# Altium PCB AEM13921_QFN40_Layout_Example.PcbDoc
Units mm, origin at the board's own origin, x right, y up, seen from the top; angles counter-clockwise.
Board outline 76 x 49 mm, 4 copper layers (Component Side, Ground Plane, Power Plane, Solder Side), stack 1.563 mm thick; 19 components, 42 nets, 78 pads, 29 vias.
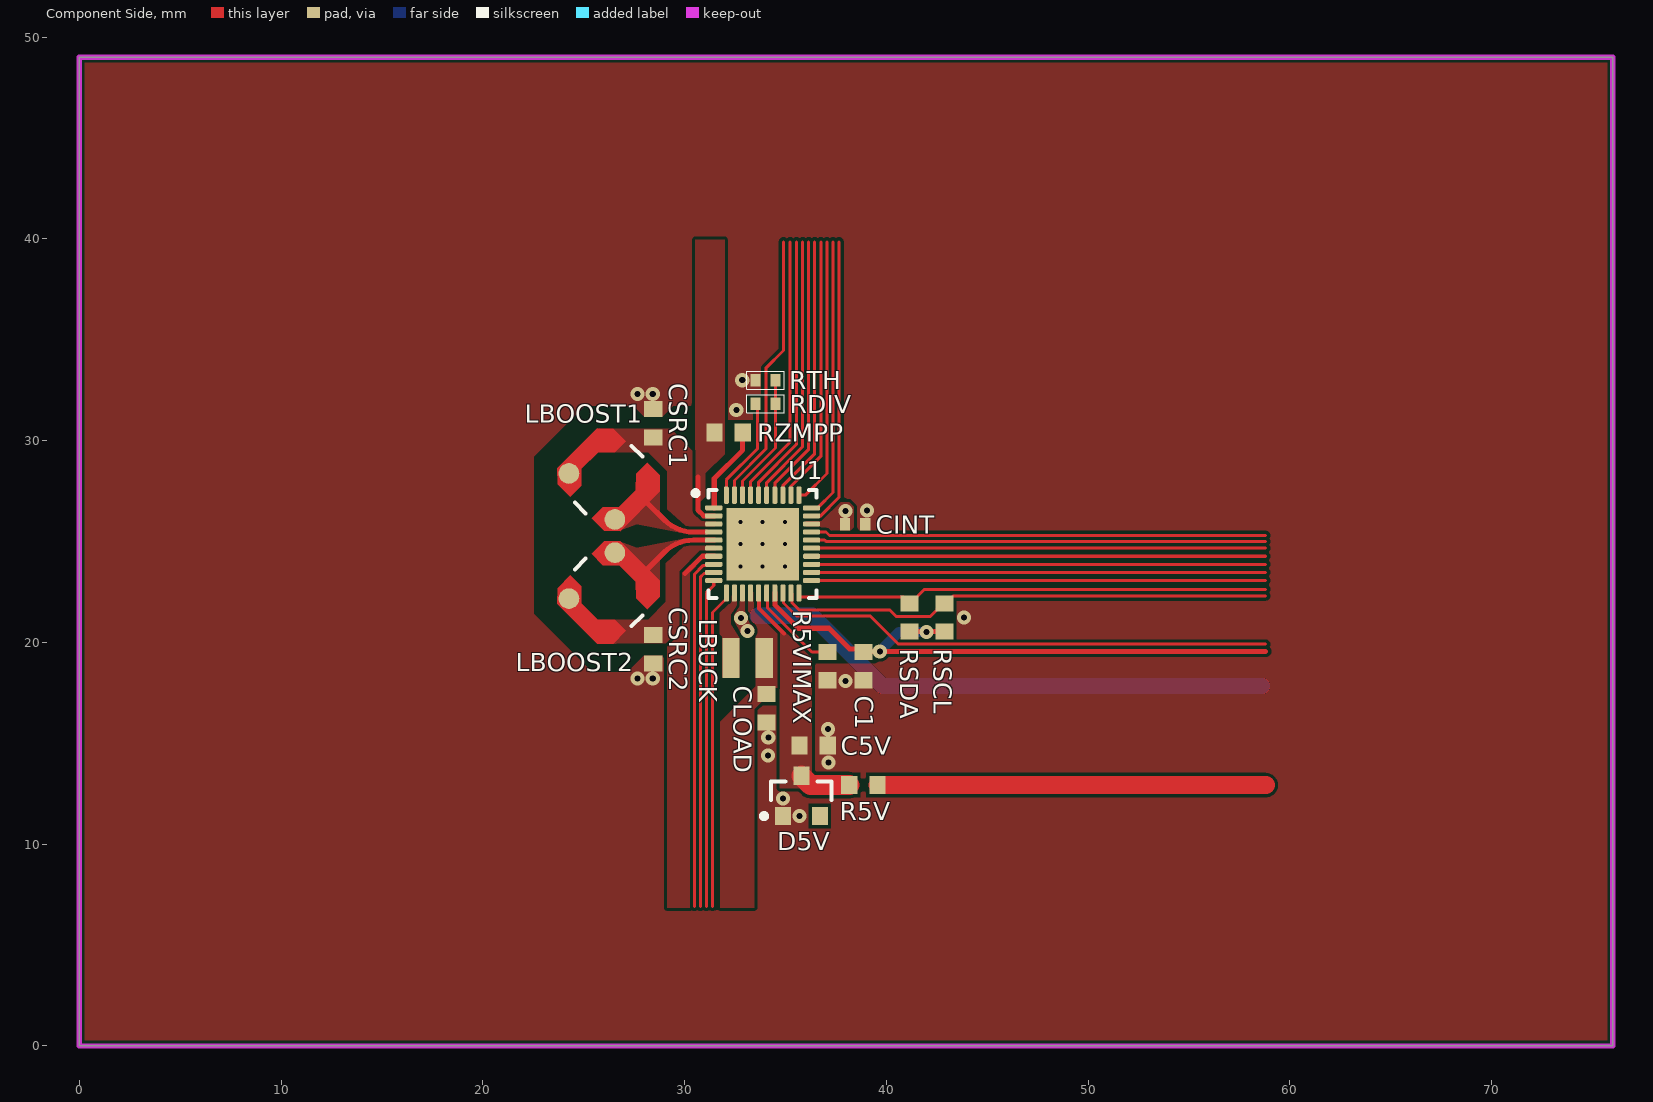
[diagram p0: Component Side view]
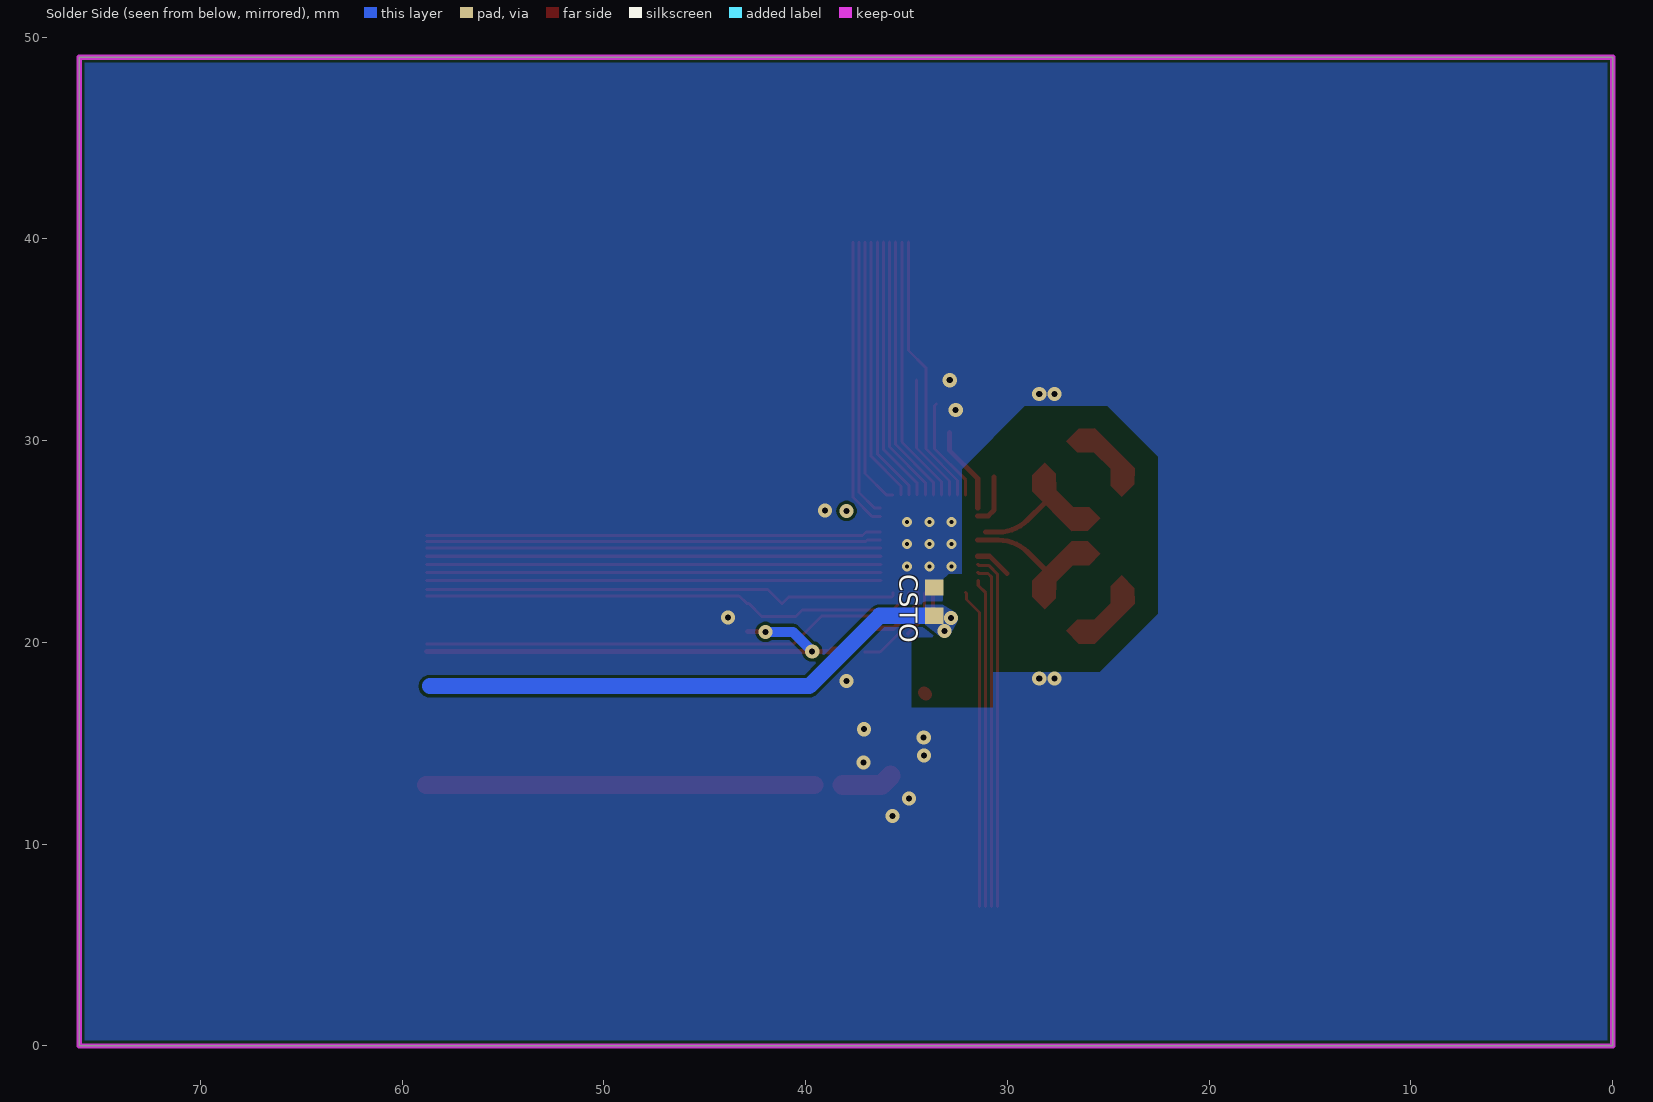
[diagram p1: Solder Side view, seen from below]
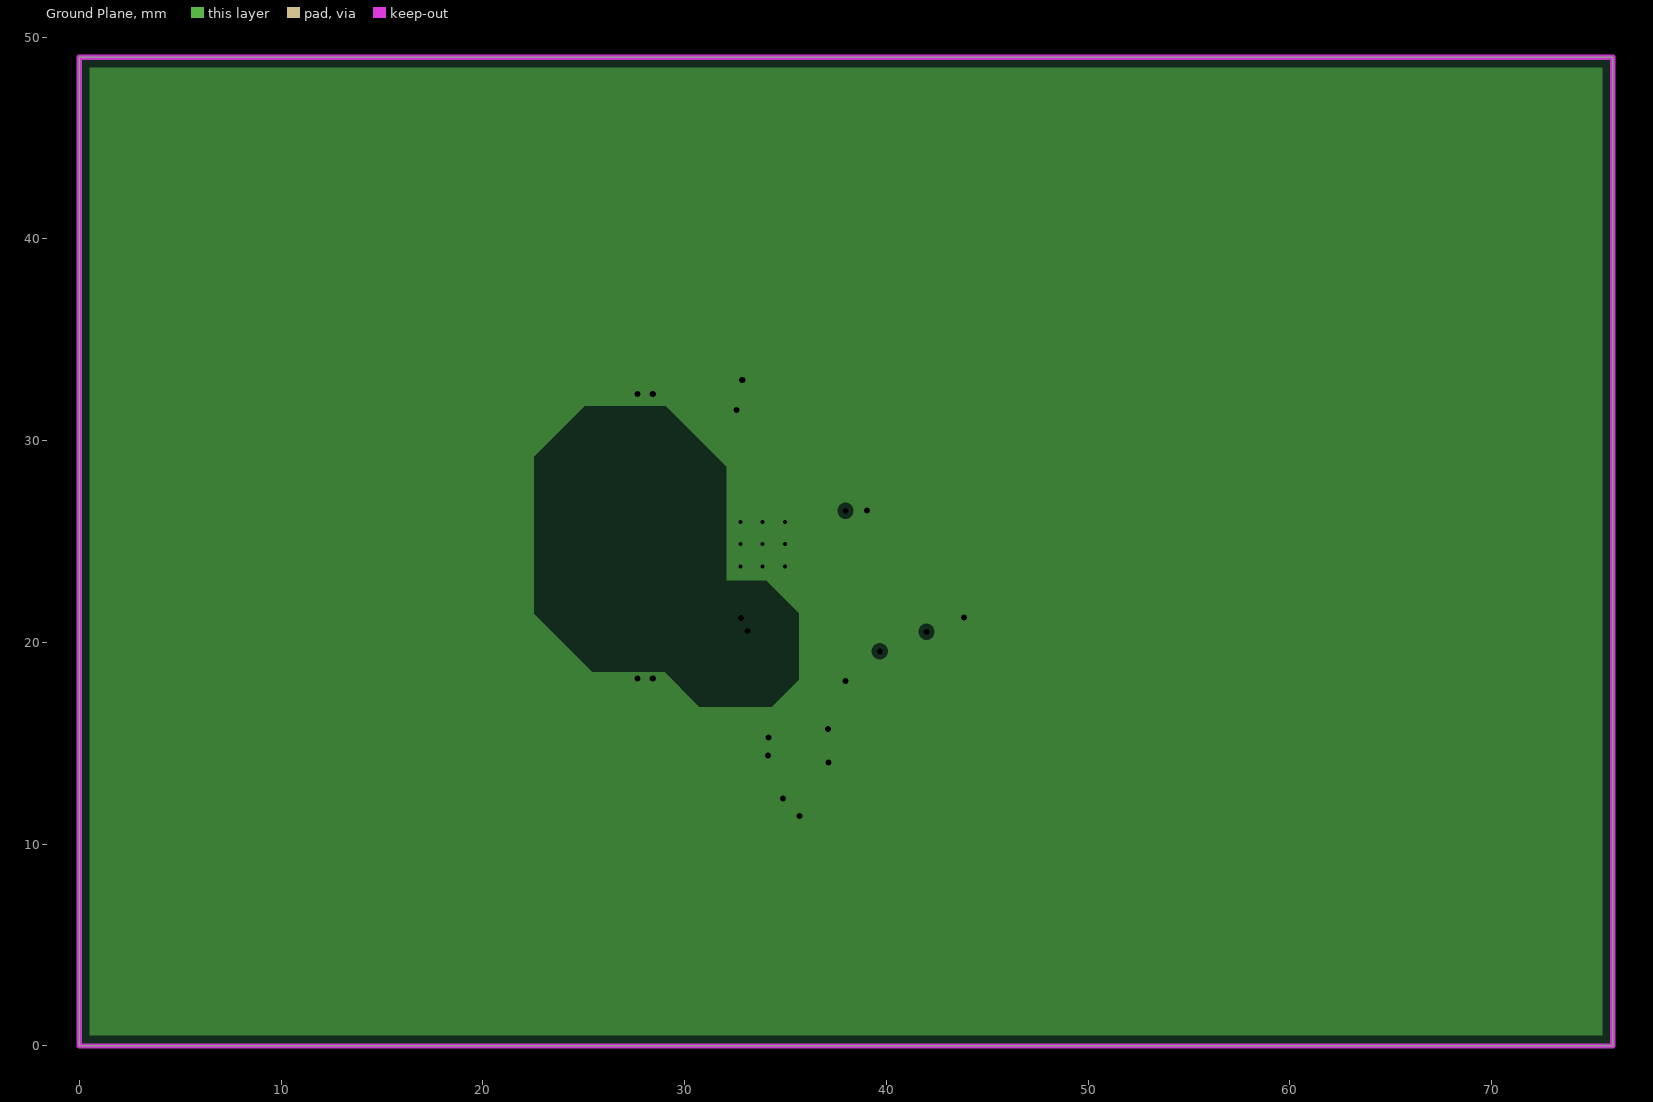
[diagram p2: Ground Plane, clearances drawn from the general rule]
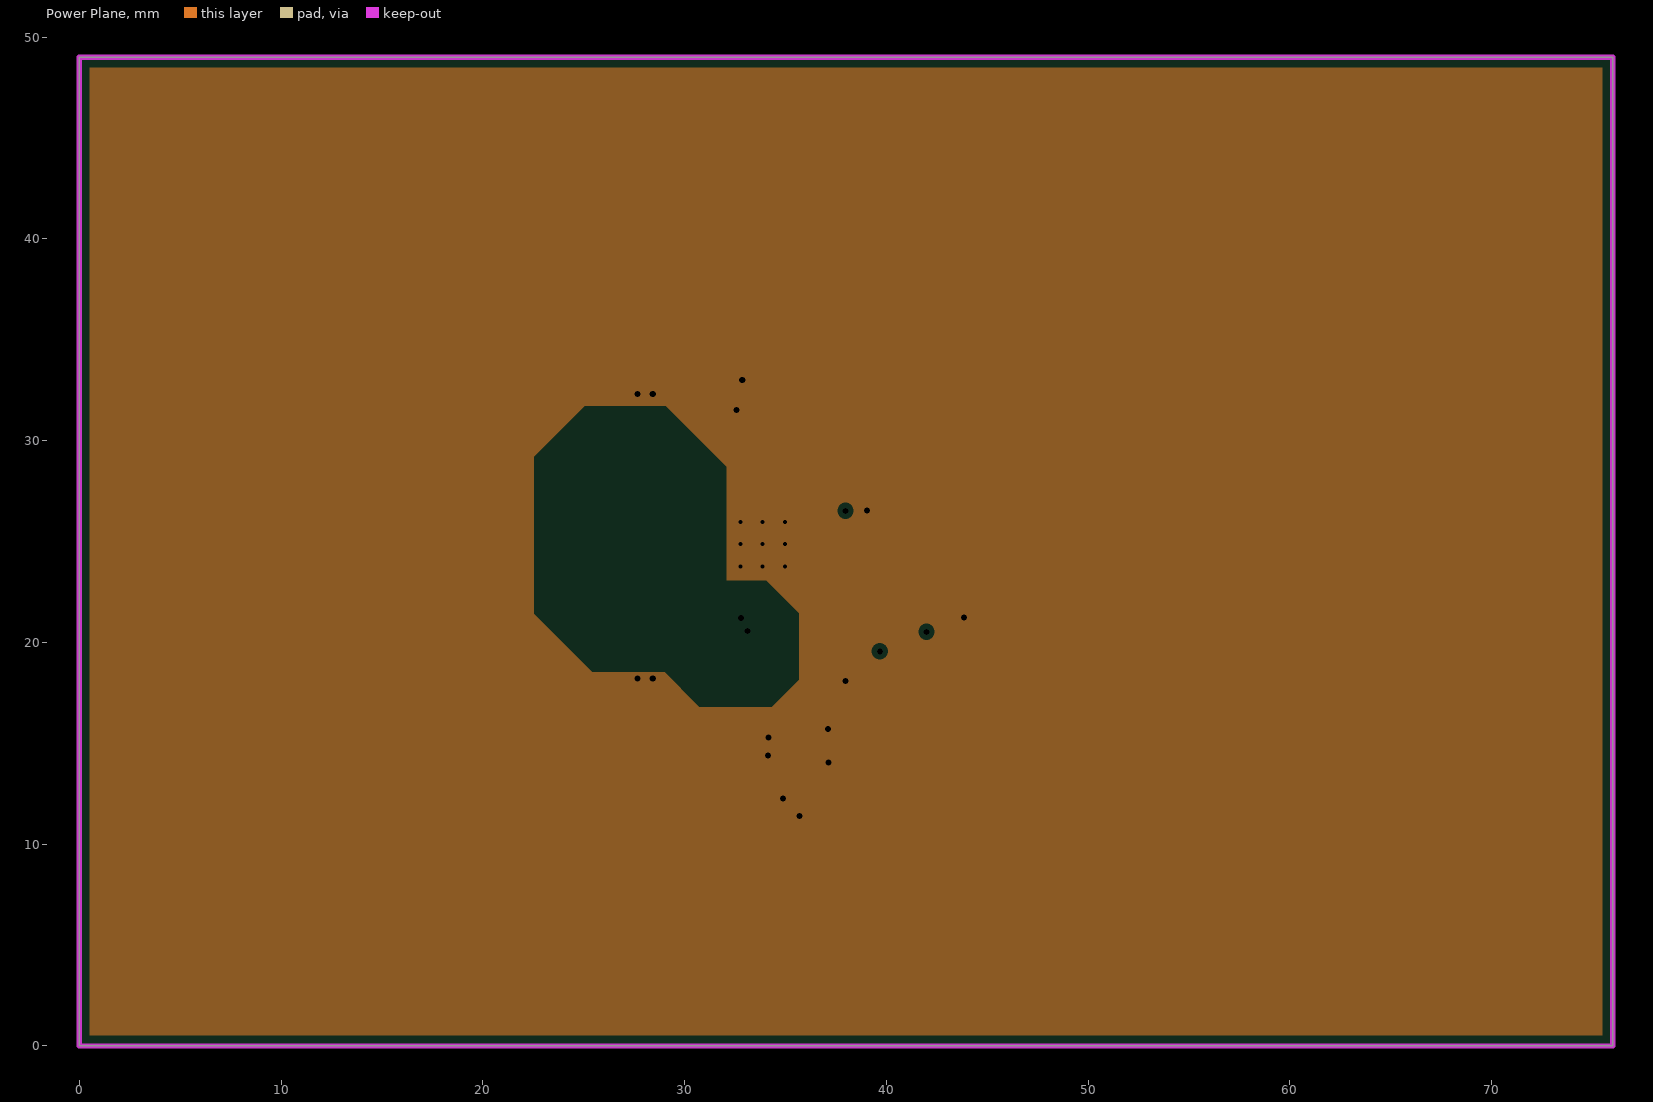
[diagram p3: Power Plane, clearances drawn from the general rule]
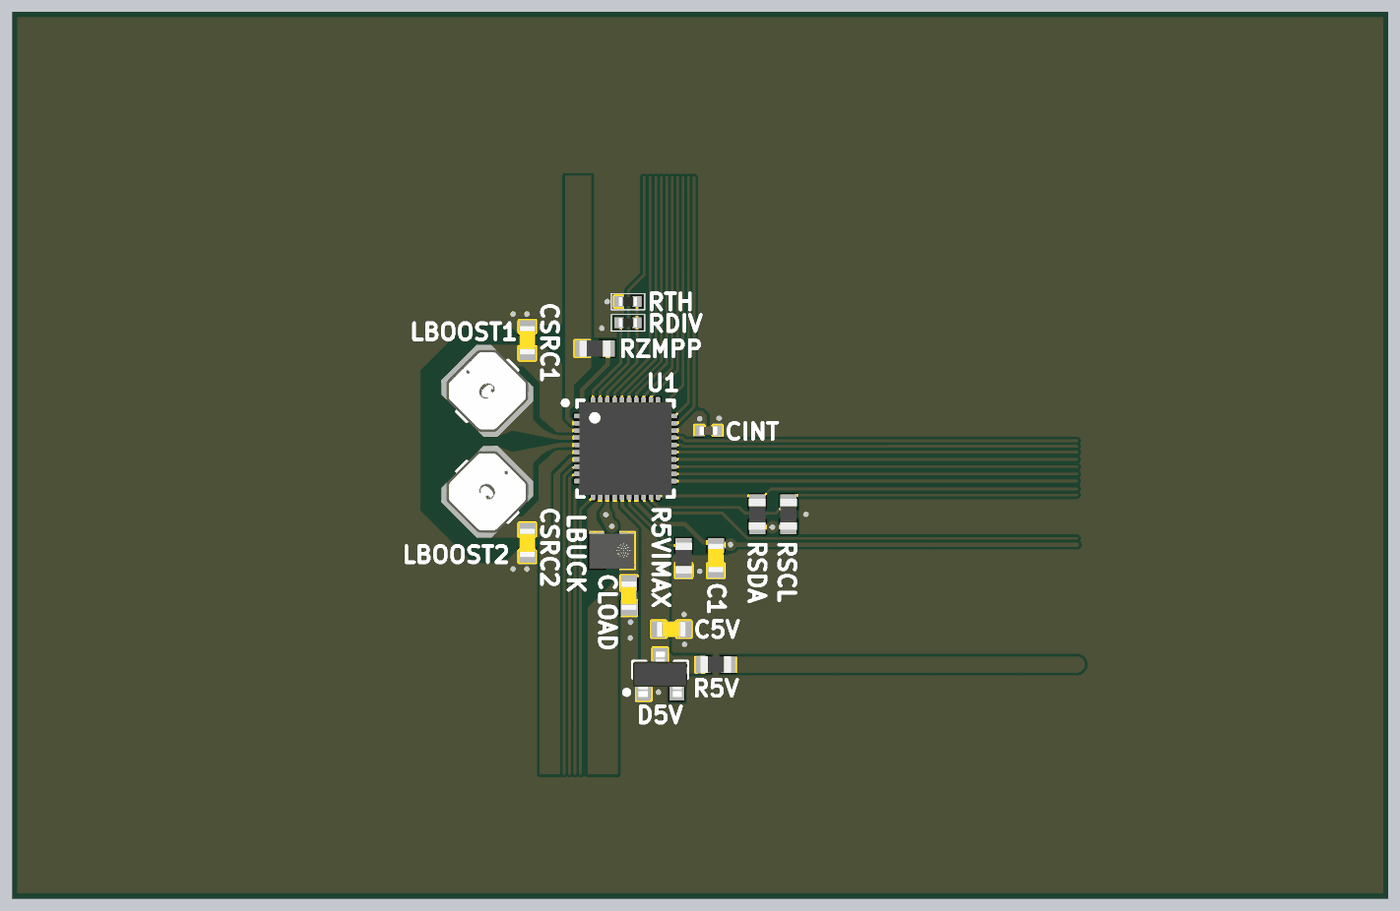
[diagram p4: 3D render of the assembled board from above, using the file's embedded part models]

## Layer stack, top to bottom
Top Solder: solder mask 0.0102, Solder Resist, Dk 3.5
Component Side: signal copper 0.0356
Dielectric 1: prepreg 0.36, Prepreg 7628, Dk 4.2
Ground Plane: plane copper 0.036, net GND
Dielectric 3: core 0.7, Core, Dk 4.2
Power Plane: plane copper 0.036, net (Multiple Nets)
Dielectric 4: prepreg 0.36, Prepreg 7628, Dk 4.2
Solder Side: signal copper 0.0356
Bottom Solder: solder mask 0.0102, Solder Resist, Dk 3.5

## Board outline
0,0 0,49 76,49 76,0

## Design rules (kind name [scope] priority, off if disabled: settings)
Clearance Clearance_SW [InNetClass('SW') and not InComponent('U1') vs InNet('GND')] p1: gap=0.15 ignorepadtopadclearanceinfootprint=FALSE except(0.5: Arc-Poly Track-Poly SMDPad-Poly THPad-Poly Via-Poly Fill-Poly Poly-Poly Poly-Region)
Clearance [All] p2: gap=0.15 ignorepadtopadclearanceinfootprint=FALSE
ComponentClearance ComponentClearance_DIL [HasFootprint('DIL_PAD') vs HasFootprint('DIL_PAD')] p1: gap=0 collisioncheckmode=3 verticalgap=0 showdistances=FALSE
ComponentClearance [All] p2: gap=0.254 collisioncheckmode=3 verticalgap=0.254 showdistances=FALSE
DiffPairsRouting [All] p1: maxlimit=0.254 minlimit=0.254 mostfreqgap=0.254 toplayer_minwidth=0.381 toplayer_maxwidth=0.381 toplayer_prefwidth=0.381 bottomlayer_minwidth=0.381 bottomlayer_maxwidth=0.381 bottomlayer_prefwidth=0.381 substack1={24748C9E-C2FE-4590-BE0C-AD6E21E98903} toplayer_{24748c9e-c2fe-4590-be0c-ad6e21e98903}_minwidth=0.381 toplayer_{24748c9e-c2fe-4590-be0c-ad6e21e98903}_maxwidth=0.381 toplayer_{24748c9e-c2fe-4590-be0c-ad6e21e98903}_prefwidth=0.381 bottomlayer_{24748c9e-c2fe-4590-be0c-ad6e21e98903}_minwidth=0.381 bottomlayer_{24748c9e-c2fe-4590-be0c-ad6e21e98903}_maxwidth=0.381 bottomlayer_{24748c9e-c2fe-4590-be0c-ad6e21e98903}_prefwidth=0.381 substack2={CAEF0C9C-1F67-4FFA-A1CA-0FD6FF6C2F90} toplayer_{caef0c9c-1f67-4ffa-a1ca-0fd6ff6c2f90}_minwidth=0.381 toplayer_{caef0c9c-1f67-4ffa-a1ca-0fd6ff6c2f90}_maxwidth=0.381 toplayer_{caef0c9c-1f67-4ffa-a1ca-0fd6ff6c2f90}_prefwidth=0.381 bottomlayer_{caef0c9c-1f67-4ffa-a1ca-0fd6ff6c2f90}_minwidth=0.381 bottomlayer_{caef0c9c-1f67-4ffa-a1ca-0fd6ff6c2f90}_maxwidth=0.381 bottomlayer_{caef0c9c-1f67-4ffa-a1ca-0fd6ff6c2f90}_prefwidth=0.381 substack3={D99B185B-21CD-406C-9F05-D1849F64E374} toplayer_{d99b185b-21cd-406c-9f05-d1849f64e374}_minwidth=0.381 toplayer_{d99b185b-21cd-406c-9f05-d1849f64e374}_maxwidth=0.381 toplayer_{d99b185b-21cd-406c-9f05-d1849f64e374}_prefwidth=0.381 bottomlayer_{d99b185b-21cd-406c-9f05-d1849f64e374}_minwidth=0.381 bottomlayer_{d99b185b-21cd-406c-9f05-d1849f64e374}_maxwidth=0.381 bottomlayer_{d99b185b-21cd-406c-9f05-d1849f64e374}_prefwidth=0.381 maxuncoupledlength=12.7
HoleToHoleClearance [All] p1: gap=0.2 allowstackedmicrovias=TRUE
MinimumAnnularRing [All] p1: minimumring=0.15
MinimumSolderMaskSliver [All] p1: minsoldermaskwidth=0.01
PlaneClearance [All] p1: clearance=0.254
PlaneConnect PlaneConnect_2.54mm_headers [InComponent('M1') or InComponent('M2') or InComponent('M3') or InComponent('M4')] p1: planeconnectstyle=Direct reliefexpansion=0.508 reliefentries=4 reliefconductorwidth=0.5 reliefairgap=0.254
PlaneConnect [All] p2: pad.planeconnectstyle=Relief pad.reliefexpansion=0.2 pad.reliefentries=4 pad.reliefconductorwidth=0.5 pad.reliefairgap=0.15 via.planeconnectstyle=Direct via.reliefexpansion=0.2 via.reliefentries=4 via.reliefconductorwidth=0.254 via.reliefairgap=0.15
PolygonConnect PolygonConnect_1 [InComponent('M1') or InComponent('M2') or InComponent('M3') or InComponent('M4')] p1: connectstyle=Direct reliefconductorwidth=0.254 reliefentries=4 polygonreliefangle="90 Angle" airgapwidth=0.254
PolygonConnect [All] p2: thpad.connectstyle=Relief thpad.reliefconductorwidth=0.35 thpad.reliefentries=4 thpad.polygonreliefangle="90 Angle" thpad.airgapwidth=0.15 smdpad.connectstyle=Direct smdpad.reliefconductorwidth=0.5 smdpad.reliefentries=4 smdpad.polygonreliefangle="90 Angle" smdpad.airgapwidth=0.15 via.connectstyle=Direct via.reliefconductorwidth=0.35 via.reliefentries=4 via.polygonreliefangle="90 Angle" via.airgapwidth=0.15
RoutingVias [All] p1: holewidth=0.3 width=0.7 viastyle="Through Hole" minholewidth=0.3 minwidth=0.7 maxholewidth=0.3 maxwidth=0.7
SilkToSilkClearance [All] p1: silktosilkclearance=0
SilkToSolderMaskClearance [IsPad] p1: minsilkscreentomaskgap=0.1 clearancetoexposedcopper=TRUE
SolderMaskExpansion "tented vias" [IsVia] p1: expansion=0.15 istentingtop=TRUE
SolderMaskExpansion [All] p2: expansion=0.09 istentingtop=FALSE
SupplyNets "Schematic Supply Nets_3" [InNet('STO')] p1: voltage=0.000
SupplyNets "Schematic Supply Nets_2" [InNet('VDDIO')] p2: voltage=0.000
SupplyNets "Schematic Supply Nets_1" [InNet('VINT')] p3: voltage=0.000
SupplyNets "Schematic Supply Nets" [InNet('GND')] p4: voltage=0.000
Width [All] p1: maxlimit=2 minlimit=0.15 preferedwidth=0.2 substack1={24748C9E-C2FE-4590-BE0C-AD6E21E98903} substack2={CAEF0C9C-1F67-4FFA-A1CA-0FD6FF6C2F90} substack3={D99B185B-21CD-406C-9F05-D1849F64E374} minimp=50.000000 maximp=50.000000 favimp=50.000000
22 further rules are at their usual default settings.

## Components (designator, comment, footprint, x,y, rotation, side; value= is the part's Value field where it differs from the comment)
C1 "10uF" 0603_[1608] 38.862,18.821 r90 top
C5V "Cap Ceramic 0603 TBD" 0603_[1608] 36.398,14.884 r180 top value=TBD
CINT "10uF" 0402_[1005] 38.456,25.857 r180 top
CLOAD "22uF" 0603_[1608] 34.061,16.739 r90 top
CSRC1 "22uF" 0603_[1608] 28.448,30.861 r270 top
CSRC2 "22uF" 0603_[1608] 28.448,19.66 r90 top
CSTO "47uF" 0603_[1608] 33.63,22.022 r270 bottom
D5V "5V1" "SOT23-3P  3x1.40mm Pitch=0.915mm diode AK" 35.789,12.395 r90 top
LBOOST1 "33uH" Coilcraft-LPS4018 26.238,28.063 r315 top
LBOOST2 "33uH" Coilcraft-LPS4018 26.238,22.477 r225 top
LBUCK "10µH" Inductor_VLS252012 33.122,19.228 r180 top
R5V "TBD" Resistor_0603_[1608] 38.862,12.929 r180 top
R5VIMAX "TBD" Resistor_0603_[1608] 37.084,18.821 r90 top
RDIV "22K" Resistor_0402 34.011,31.826 r0 top
RSCL "1kR" Resistor_0603_[1608] 42.875,21.234 r90 top
RSDA "1kR" Resistor_0603_[1608] 41.148,21.234 r90 top
RTH "10kR" Resistor_0402 34.011,32.995 r0 top
RZMPP "TBD" Resistor_0603_[1608] 32.182,30.404 r0 top
U1 "AEM13921_QFN40" QFN40_5x5mm_pitch0.4mm_ASE_98A0040QN185 33.871,24.87 r0 top locked

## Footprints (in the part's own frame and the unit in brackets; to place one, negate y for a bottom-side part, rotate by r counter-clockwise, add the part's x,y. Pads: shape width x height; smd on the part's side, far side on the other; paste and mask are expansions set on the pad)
0402_[1005] [mm] "Chip Capacitor, Body 1.0x0.5mm, IPC High Density"
  rect 0.5x0.6 smd: 1(-0.5,0) 2(0.5,0)
  body extent -0.5,-0.25 0.5,0.25, height 0.7
0603_[1608] [mm] "Chip Capacitor, Body 1.6x0.8mm, IPC High Density"
  rect 0.8x0.9 smd: 1(-0.7,0) 2(0.7,0)
  body extent -0.8,-0.43 0.8,0.43, height 0.8
Coilcraft-LPS4018 [mm]
  round 1.026 smd paste+0 mask+0: 1(-1.611,-1.175) 2(1.611,-1.175)
  Component Side region: -0.75,1.945 -1.64,1.945 -2.2,1.395 -2.2,-1.395 -1.64,-1.945 -0.75,-1.945 -0.75,-1.17 -1.33,-0.575 -1.33,0.575 -0.75,1.17
  Component Side region: 0.75,1.945 1.64,1.945 2.2,1.395 2.2,-1.395 1.64,-1.945 0.75,-1.945 0.75,-1.17 1.33,-0.575 1.33,0.575 0.75,1.17
  silkscreen extent -0.37,-1.99 0.37,1.99, body extent -2.3,-2.09 2.3,2.09, height 0.25
Inductor_VLS252012 [mm]
  rect 0.85x2 smd: 1(-0.825,0) 2(0.825,0)
  body extent -1.25,-1 1.25,1, height 1.2
QFN40_5x5mm_pitch0.4mm_ASE_98A0040QN185 [mm] "QFN40 body 5x5mm pitch 0.4mm Manufacturer ASE"
  rrect50% 0.85x0.25 smd: 1(-2.425,1.8) 2(-2.425,1.4) 3(-2.425,1) 4(-2.425,0.6) 5(-2.425,0.2) 6(-2.425,-0.2) 7(-2.425,-0.6) 8(-2.425,-1) 9(-2.425,-1.4) 10(-2.425,-1.8) 21(2.425,-1.8) 22(2.425,-1.4) 23(2.425,-1) 24(2.425,-0.6) 25(2.425,-0.2) 26(2.425,0.2) 27(2.425,0.6) 28(2.425,1) 29(2.425,1.4) 30(2.425,1.8)
  rrect50% 0.25x0.85 smd: 11(-1.8,-2.425) 12(-1.4,-2.425) 13(-1,-2.425) 14(-0.6,-2.425) 15(-0.2,-2.425) 16(0.2,-2.425) 17(0.6,-2.425) 18(1,-2.425) 19(1.4,-2.425) 20(1.8,-2.425) 31(1.8,2.425) 32(1.4,2.425) 33(1,2.425) 34(0.6,2.425) 35(0.2,2.425) 36(-0.2,2.425) 37(-0.6,2.425) 38(-1,2.425) 39(-1.4,2.425) 40(-1.8,2.425)
  rect 3.6x3.6 smd: 41(0,0)
  silkscreen extent -3.45,-2.67 2.67,2.68, body extent -2.55,-2.55 2.55,2.55, height 1
Resistor_0402 [mm]
  rect 0.5x0.6 smd: 1(-0.5,0) 2(0.5,0)
  silkscreen extent -0.92,-0.45 0.92,0.45, body extent -0.5,-0.25 0.5,0.25, height 0.3
Resistor_0603_[1608] [mm]
  rect 0.8x0.9 smd: 1(-0.7,0) 2(0.7,0)
  body extent -0.85,-0.46 0.85,0.46, height 0.56
"SOT23-3P  3x1.40mm Pitch=0.915mm diode AK" [mm] "SOT23, 3-Leads, Body 3x1.40mm, Pitch 0.915mm"
  rect 0.9x0.8 smd: A(-1,0.915) K(1,0) NC(-1,-0.915)
  silkscreen extent -1.12,-1.5 0.7,1.97, body extent -1.25,-1.5 1.25,1.5, height 1.1

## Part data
C1: library part "Cap Ceramic 10uF, 10V, 20%, X5R 0603", "Cap Ceramic 10uF, 10V, 20%, X5R 0603", Manuf=MURATA, Manuf PN=GRM188R61A106ME69D, Package=0603, Package Metric=1608
C5V: Package=0603, Package Metric=1608
CINT: library part "Cap Ceramic 10uF, 6.3V, 20%, X5R, 0402", "Cap Ceramic 10uF, 6.3V, 20%, X5R, 0402", Manuf=MURATA, Manuf PN=GRM155R60J106ME44D, Package=0402, Package Metric=1005
CLOAD CSRC1 CSRC2: library part "Cap Ceramic 22uF, 10V, 20%, X5R 0603", "Cap Ceramic 22uF, 10V, 20%, X5R 0603", Manuf=MuRata, Manuf PN=GRM188R61A226ME15D, Package=0603, Package Metric=1608
CSTO: library part "Cap Ceramic 47uF 6.3V +/-20% X5R 0603", "Cap Ceramic 47uF 6.3V +/-20% X5R 0603", Manuf=Murata, Manuf PN=GRM188R60J476ME15D, Package=0603, Package Metric=1608
D5V: library part "Zener 5.1V 350mW BZX84C5V1-TP", "Zener Diode 5.1 V 350 mW ±5% Surface Mount SOT-23", Manuf="Micro Commercial Co", Manuf PN=BZX84C5V1-TP
LBOOST1 LBOOST2: library part "Power Inductor 33uH - 0,68A - LPS4018 - Small Symbol", "Power Inductor 33uH - 0,68A - LPS4018", Manuf=Coilcraft, Manuf PN=LPS4018-333MRB, Max DC Current=800mA, Package="4 x 4 x 1.8mm", Self Resonant Frequency=20MHz
LBUCK: library part "Power Inductor 10µH TDK VLS-CX-1", "Power Inductor 10µH TDK VLS-CX-1", Manuf=TDK, Manuf PN=VLS252012CX-100M-1, Max DC Current="970 mA", Package=2520
R5V R5VIMAX RZMPP: library part "Resistor TBD - 0603", "Resistor TBD - 0603", Package=0402
RDIV: library part "Resistor 22KR - 0402 - 50V", "Resistor 22KR - 0402 - 50V", Manuf=Yageo, Manuf PN=RC0402FR-0722KL, Package=0402
RSCL RSDA: library part "Resistor 1kOhm - 0603 - 75V - 1%", Manuf=Multicomp, Manuf PN=MCWR06X1001FTL, Package=0603, Package Metric=1608
RTH: library part "Thermistor 10kR CTN 0402", "Thermistor 10kR CTN 0402", Manuf=Murata, Manuf PN=NCP15XH103J03RC, Package=0402
U1: library part "AEM13921 QFN40", "AEM13921 QFN40", Manuf=e-peas, Manuf PN=10AEM13921J0000, Package=QFN40

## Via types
v1: diameter 0.7, hole 0.3, Component Side to Solder Side, tented both sides, 20 vias
v2: diameter 0.5, hole 0.2, Component Side to Solder Side, tented both sides, 9 vias

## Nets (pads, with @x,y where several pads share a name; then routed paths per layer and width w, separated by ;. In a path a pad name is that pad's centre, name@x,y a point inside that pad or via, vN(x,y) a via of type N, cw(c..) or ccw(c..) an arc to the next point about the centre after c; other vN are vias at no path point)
5V_IMAX: R5VIMAX.2 U1.16 | length 4.7
  Component Side w0.15: U1.16@34.071,22.47 34.1,22.44 34.1,21.729 36.308,19.521 R5VIMAX.2
5V_IN: C5V.2 D5V.K R5V.2 U1.15 | length 5.1
  Component Side w0.2: U1.15@33.69,22.422 33.69,21.678 34.931,20.438
  Component Side w1: D5V.K 36.255,12.929 R5V.2
5V_IN_EXT: R5V.1 | length 19.2
  Component Side w0.9: R5V.1 58.8,12.929
BUFSRC1: CSRC1.2 LBOOST1.1 U1.3
BUFSRC2: CSRC2.2 LBOOST2.2 U1.6
GND: C1.1 C5V.1 CINT.1 CLOAD.1 CSRC1.1 CSRC2.1 CSTO.1 D5V.A R5VIMAX.1 RTH.1 U1.41
  other v1: 35.687,11.405 34.874,12.268 37.135,14.046 34.138,14.402 34.149,15.278 37.109,15.697 37.973,18.085 27.661,18.212 28.423,18.212 43.84,21.234 39.04,26.543 32.563,31.521 27.661,32.309 28.423,32.309 32.857,32.995
  other v2: 32.771,23.77 33.871,23.77 34.971,23.77 32.771,24.87 33.871,24.87 34.971,24.87 32.771,25.97 33.871,25.97 34.971,25.97
IRQ: U1.18 | length 25.3
  Component Side w0.15: U1.18@34.871,22.47 34.906,22.435 34.906,21.949 35.544,21.311 39.204,21.311 40.605,19.909 58.801,19.909
LOAD: CLOAD.2 LBUCK.1 U1.14 | length 0.1
  Component Side w0.6: CLOAD.2@34.038,17.415 CLOAD.2@34.138,17.515
LOAD_CFG_0: U1.36 | length 13.3
  Component Side w0.15: U1.36@33.673,27.297 33.673,27.94 35.549,29.816 35.549,39.853
LOAD_CFG_1: U1.10 | length 16.3
  Component Side w0.15: 31.08,6.914 31.08,22.454 31.446,22.82 U1.10
LOAD_CFG_2: U1.11 | length 15.8
  Component Side w0.15: 31.38,6.914 31.38,21.479 32.031,22.131 32.031,22.431 U1.11@32.071,22.47
SCL: RSCL.2 U1.19 | length 24.7
  Component Side w0.15: U1.19@35.271,22.47 35.321,22.42 35.321,21.963 35.67,21.614 40.159,21.614 40.488,21.285 42.176,21.285 42.825,21.934 RSCL.2 42.925,21.934 43.292,22.301 58.801,22.301
SDA: RSDA.2 U1.20 | length 23.7
  Component Side w0.15: U1.20@35.671,22.47 35.671,22.306 35.717,22.259 40.823,22.259 RSDA.2 41.198,21.934 41.895,22.631 58.801,22.631
SHIP_MODE: U1.8 | length 17.7
  Component Side w0.15: 30.48,6.914 30.48,23.369 30.931,23.82 31.421,23.82 U1.8@31.471,23.87
SRC1: RZMPP.1 U1.2 | length 2.6
  Component Side w0.25: 30.66,28.188 30.66,26.553 30.943,26.27 U1.2@31.471,26.27
SRC1_CFG_0: U1.26 | length 22.5
  Component Side w0.15: U1.26 36.946,25.07 37.022,24.994 37.084,24.994 58.801,24.998
SRC1_CFG_1: U1.27 | length 22.6
  Component Side w0.15: U1.27 37.014,25.47 37.183,25.301 58.801,25.301
SRC1_CFG_2: U1.29 | length 14.4
  Component Side w0.15: U1.29@36.293,26.229 36.694,26.229 37.654,27.189 37.654,39.853
SRC1_CFG_3: U1.30 | length 13.8
  Component Side w0.15: U1.30 36.596,26.67 37.354,27.428 37.354,39.853
SRC1_CFG_4: U1.31 | length 13.3
  Component Side w0.15: U1.31 35.982,27.295 37.054,28.367 37.054,39.853
SRC1_MODE: U1.25 | length 22.5
  Component Side w0.15: U1.25@36.271,24.67 58.801,24.67
SRC2: U1.7 | length 1.8
  Component Side w0.25: 30.03,23.422 30.877,24.27 U1.7@31.471,24.27
SRC2_CFG_0: U1.33 | length 13.2
  Component Side w0.15: U1.33 34.871,27.766 36.449,29.345 36.449,39.853
SRC2_CFG_1: U1.34 | length 13.3
  Component Side w0.15: U1.34 34.471,27.889 36.149,29.568 36.149,39.853
SRC2_CFG_2: U1.35 | length 13.3
  Component Side w0.15: U1.35 34.071,27.913 35.849,29.692 35.849,39.853
SRC2_CFG_3: U1.37 | length 13.4
  Component Side w0.15: U1.37 33.271,27.962 35.23,29.921 35.23,39.853
SRC2_CFG_4: U1.39 | length 13.6
  Component Side w0.15: U1.39 32.471,28.026 34.025,29.58 34.025,33.593 34.9,34.468 34.9,39.853
SRC2_MODE: U1.32 | length 13.2
  Component Side w0.15: U1.32 35.271,27.742 36.754,29.225 36.754,39.853
ST_LOAD: U1.9 | length 17.1
  Component Side w0.15: 30.78,6.914 30.78,23.236 30.964,23.42 31.421,23.42 U1.9@31.471,23.47
ST_STO: U1.21 | length 22.5
  Component Side w0.15: U1.21@36.271,23.07 58.801,23.07
STO: CSTO.2 U1.13 | length 26.6
  Component Side w0.25: v1(33.122,20.574) v1@33.122,20.696
  Solder Side w0.8: CSTO.2 36.336,21.322 39.827,17.831 58.623,17.831
  other v1: 32.791,21.209
STO_CFG_0: U1.22 | length 22.5
  Component Side w0.15: U1.22@36.271,23.47 58.801,23.47
STO_CFG_1: U1.23 | length 22.5
  Component Side w0.15: U1.23@36.271,23.87 58.801,23.87
STO_CFG_2: U1.24 | length 22.5
  Component Side w0.15: U1.24@36.271,24.27 58.801,24.27
SWBOOST1: LBOOST1.2 U1.4 | length 3.4
  Component Side w0.25: 28.181,26.886 29.005,26.063 ccw(c30.435,27.494) 30.435,25.47 U1.4@31.09,25.47
SWBOOST2: LBOOST2.1 U1.5 | length 4.3
  Component Side w0.25: 27.813,23.286 29.005,24.477 cw(c30.435,23.046) 30.435,25.07 U1.5@31.471,25.07
SWBUCK: LBUCK.2 U1.12
TH_MON: RDIV.2 RTH.2 U1.38 | length 6.4
  Component Side w0.15: U1.38 32.871,27.994 34.511,29.634 RDIV.2 RTH.2
TH_REF: RDIV.1 U1.40 | length 5.2
  Component Side w0.15: U1.40 32.071,28.057 33.625,29.612 33.625,31.712 RDIV.1
VDDIO: C1.2 RSCL.1 RSDA.1 U1.17 | length 30.4
  Component Side w0.25: U1.17@34.471,22.47 34.471,21.867 35.636,20.701 37.16,20.701 38.183,19.678 38.706,19.678 C1.2 38.899,19.558 v1(39.675,19.558) 58.801,19.558 ; RSDA.1 RSCL.1
  Solder Side w0.5: v1(39.675,19.558) 40.64,20.523 v1(41.986,20.523)
VINT: CINT.2 U1.28
  other v1: 37.973,26.518
ZMPP: RZMPP.2 U1.1 | length 4.3
  Component Side w0.25: U1.1@31.471,26.67 31.471,28.118 32.882,29.529 RZMPP.2
pads on no net: D5V.NC

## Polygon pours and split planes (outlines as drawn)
GND on Component Side "NONET_L-01_P-001" (solid, remove dead copper, pour order 44): 0,49 76,49 76,0 0,0
BUFSRC2 on Component Side "NONET_L-01_P-001" (solid, remove dead copper, pour order 32): 25.679,19.933 25.679,20.238 26.391,20.949 26.391,20.974 26.543,21.127 28.194,21.127 29.073,22.006 29.073,23.927 30.023,24.784 31.521,24.784 31.674,24.632 31.674,24.556 30.763,24.556 29.743,23.536 29.743,20.625 29.073,19.955
LOAD on Component Side "NONET_L-01_P-001" (solid, pour order 27): 33.147,22.479 33.147,21.438 33.522,20.742 33.522,17.755 34.595,17.755 34.595,20.777 33.604,21.768 33.604,22.479
VINT on Component Side "NONET_L-01_P-001" (solid, pour order 26): 36.017,26.01 36.728,26.01 37.668,26.949 38.151,26.949 38.379,26.721 38.379,25.705 38.228,25.553 37.193,25.545 37.078,25.66 36.017,25.66
SWBUCK on Component Side "NONET_L-01_P-001" (solid, pour order 45): 32.596,22.318 32.289,22.318 32.289,21.999 31.75,21.459 31.75,20.4 31.872,20.279 31.872,18.279 32.722,18.279 32.722,20.228 32.289,20.898 32.289,21.384 32.596,21.801
STO on Component Side "CCCC" (solid, pour order 39): 32.741,22.555 32.741,21.793 32.467,21.361 32.467,21.083 32.852,20.345 33.274,20.345 33.401,20.345 33.447,20.692 33.024,21.51 32.995,22.555
5V_IN on Component Side "NONET_L-01_P-001" (solid, pour order 40): 33.833,21.412 34.722,20.523 34.722,12.776 36.297,12.776 36.297,19.38 34.239,21.438
LOAD on Component Side "NONET_L-01_P-001" (solid, pour order 43): 33.452,16.688 34.592,17.828 34.592,17.915 33.616,17.915 31.775,16.075 31.775,6.858 33.452,6.858
SWBOOST1 on Component Side "NONET_L-01_P-001" (solid, pour order 28): 28.778,27.508 28.778,26.467 29.718,25.527 30.582,25.527 30.759,25.349 30.057,25.38 27.635,25.857 26.752,25.527 26.518,25.552
SWBOOST2 on Component Side "NONET_L-01_P-001" (solid, pour order 29): 28.778,23.032 28.778,24.073 29.718,25.013 30.582,25.013 30.759,25.191 30.057,25.16 27.635,24.683 26.752,25.013 26.518,24.988
BUFSRC1 on Component Side "NONET_L-01_P-001" (solid, pour order 30): 25.679,30.607 25.679,30.302 26.391,29.591 26.391,29.566 26.543,29.413 28.194,29.413 29.134,28.473 29.134,26.594 30.099,25.756 31.521,25.756 31.674,25.908 31.674,25.984 30.988,25.984 30.383,26.589 30.383,29.51 29.309,30.584
SRC1 on Component Side "NONET_L-01_P-001" (solid, pour order 33): 31.026,28.384 31.026,27.216 30.534,26.724 30.534,39.954 31.979,39.954 31.979,29.337
SRC2 on Component Side "NONET_L-01_P-001" (solid, pour order 38): 29.842,20.495 29.842,23.41 30.257,23.825 30.531,23.825 30.625,23.731 30.404,23.51 30.404,6.858 29.134,6.858 29.134,19.787
GND on Solder Side "NONET_L-01_P-001" (solid, remove dead copper, pour order 42): 0,49 76,49 76,0 0,0
STO on Solder Side "NONET_L-01_P-001" (solid, pour order 41): 32.589,21.492 33.2,21.862 34.08,21.862 34.08,20.872 33.368,20.331 32.825,20.396 32.474,21.069
GND on Power Plane (split plane): 75.49,0.51 0.51,0.51 0.51,48.49 75.49,48.49
GND on Ground Plane (split plane): 75.49,0.51 0.51,0.51 0.51,48.49 75.49,48.49

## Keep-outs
Keep-Out Layer:
  the board outline again, w0.25

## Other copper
Component Side:
  pour cut-out: 37.534,18.974 38.412,18.974 38.412,18.999 37.534,18.999
  pour cut-out: 32.08,31.013 32.395,31.013 32.395,30.683 32.08,30.683
  pour cut-out: 35.662,26.673 35.662,23.06 32.067,23.06 32.067,26.673
  pour cut-out: 43.459,21.082 43.459,21.412 43.434,21.412 43.434,21.082
  pour cut-out: 27.981,19.37 28.898,19.37 28.898,19.939 25.629,19.939 23.673,21.895 23.673,28.6 25.679,30.607 30.296,30.607 30.321,31.699 29.436,31.699 28.898,31.161 27.998,31.161 27.46,31.699 25.044,31.699 22.555,29.21 22.555,21.412 25.425,18.542 27.153,18.542
Solder Side:
  pour cut-out: 30.734,22.257 31.859,23.382 32.92,23.382 33.18,23.122 33.18,21.989 33.108,21.917 32.661,21.917 32.233,21.488 32.233,20.292 32.297,20.228 34.747,20.228 34.747,16.789 30.734,16.789
  pour cut-out: 29.136,31.699 32.25,28.586 32.25,18.542 28.524,18.542 25.425,18.542 22.555,21.412 22.555,29.21 25.044,31.699
Ground Plane (plane layer: these items are gaps in the copper):
  pour cut-out: 25.044,31.699 22.555,29.21 22.555,21.412 25.425,18.542 29.007,18.542 32.055,21.59 32.055,28.702 29.058,31.699
  pour cut-out: 34.036,23.063 35.662,21.438 35.662,18.161 34.315,16.815 30.734,16.815 28.931,18.618 28.931,20.041 31.953,23.063
Power Plane (plane layer: these items are gaps in the copper):
  pour cut-out: 34.036,23.063 35.662,21.438 35.662,18.161 34.315,16.815 30.734,16.815 28.931,18.618 28.931,20.041 31.953,23.063
  pour cut-out: 25.044,31.699 22.555,29.21 22.555,21.412 25.425,18.542 29.007,18.542 32.055,21.59 32.055,28.702 29.058,31.699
